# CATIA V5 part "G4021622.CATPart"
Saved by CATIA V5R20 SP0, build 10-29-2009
Part number: G4021622
Revision: 12
Definition: design
Nomenclature: G4021622
Source: made
Description: NOT SPECIFIED
Bounding box of the stored display mesh (mm): x -12 to 22, y -12.803 to 12.803, z -13 to 13
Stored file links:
  C:\Users\Raffaele\Desktop\3D X SITO CF\BOLEX\26-BUSH REF 402\G4021622.CATPart
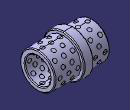
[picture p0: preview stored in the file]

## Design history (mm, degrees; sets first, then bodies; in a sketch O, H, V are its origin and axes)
Body1 "MANIFOLD_SOLID_BREP #9131" (main body)
  Solid1: solid without history
Body2 "MANIFOLD_SOLID_BREP #9274"
  Solid2: solid without history
Body3 "MANIFOLD_SOLID_BREP #9417"
  Solid3: solid without history
Body4 "MANIFOLD_SOLID_BREP #9560"
  Solid4: solid without history
Body5 "MANIFOLD_SOLID_BREP #9703"
  Solid5: solid without history
Body6 "MANIFOLD_SOLID_BREP #9848"
  Solid6: solid without history
Body7 "MANIFOLD_SOLID_BREP #9993"
  Solid7: solid without history
Body8 "MANIFOLD_SOLID_BREP #10138"
  Solid8: solid without history
Body9 "MANIFOLD_SOLID_BREP #10283"
  Solid9: solid without history
Body10 "MANIFOLD_SOLID_BREP #10428"
  Solid10: solid without history
Body11 "MANIFOLD_SOLID_BREP #10573"
  Solid11: solid without history
Body12 "MANIFOLD_SOLID_BREP #10718"
  Solid12: solid without history
Body13 "MANIFOLD_SOLID_BREP #10863"
  Solid13: solid without history
Body14 "MANIFOLD_SOLID_BREP #11008"
  Solid14: solid without history
Body15 "MANIFOLD_SOLID_BREP #11153"
  Solid15: solid without history
Body16 "MANIFOLD_SOLID_BREP #11298"
  Solid16: solid without history
Body17 "MANIFOLD_SOLID_BREP #11443"
  Solid17: solid without history
Body18 "MANIFOLD_SOLID_BREP #11586"
  Solid18: solid without history
Body19 "MANIFOLD_SOLID_BREP #11729"
  Solid19: solid without history
Body20 "MANIFOLD_SOLID_BREP #11872"
  Solid20: solid without history
Body21 "MANIFOLD_SOLID_BREP #12016"
  Solid21: solid without history
Body22 "MANIFOLD_SOLID_BREP #12161"
  Solid22: solid without history
Body23 "MANIFOLD_SOLID_BREP #12304"
  Solid23: solid without history
Body24 "MANIFOLD_SOLID_BREP #12448"
  Solid24: solid without history
Body25 "MANIFOLD_SOLID_BREP #12593"
  Solid25: solid without history
Body26 "MANIFOLD_SOLID_BREP #12738"
  Solid26: solid without history
Body27 "MANIFOLD_SOLID_BREP #12883"
  Solid27: solid without history
Body28 "MANIFOLD_SOLID_BREP #13028"
  Solid28: solid without history
Body29 "MANIFOLD_SOLID_BREP #13173"
  Solid29: solid without history
Body30 "MANIFOLD_SOLID_BREP #13318"
  Solid30: solid without history
Body31 "MANIFOLD_SOLID_BREP #13463"
  Solid31: solid without history
Body32 "MANIFOLD_SOLID_BREP #13606"
  Solid32: solid without history
Body33 "MANIFOLD_SOLID_BREP #13749"
  Solid33: solid without history
Body34 "MANIFOLD_SOLID_BREP #13892"
  Solid34: solid without history
Body35 "MANIFOLD_SOLID_BREP #14035"
  Solid35: solid without history
Body36 "MANIFOLD_SOLID_BREP #14178"
  Solid36: solid without history
Body37 "MANIFOLD_SOLID_BREP #14322"
  Solid37: solid without history
Body38 "MANIFOLD_SOLID_BREP #14467"
  Solid38: solid without history
Body39 "MANIFOLD_SOLID_BREP #14610"
  Solid39: solid without history
Body40 "MANIFOLD_SOLID_BREP #14754"
  Solid40: solid without history
Body41 "MANIFOLD_SOLID_BREP #14899"
  Solid41: solid without history
Body42 "MANIFOLD_SOLID_BREP #15044"
  Solid42: solid without history
Body43 "MANIFOLD_SOLID_BREP #15189"
  Solid43: solid without history
Body44 "MANIFOLD_SOLID_BREP #15334"
  Solid44: solid without history
Body45 "MANIFOLD_SOLID_BREP #15479"
  Solid45: solid without history
Body46 "MANIFOLD_SOLID_BREP #15624"
  Solid46: solid without history
Body47 "MANIFOLD_SOLID_BREP #15769"
  Solid47: solid without history
Body48 "MANIFOLD_SOLID_BREP #15914"
  Solid48: solid without history
Body49 "MANIFOLD_SOLID_BREP #16059"
  Solid49: solid without history
Body50 "MANIFOLD_SOLID_BREP #16204"
  Solid50: solid without history
Body51 "MANIFOLD_SOLID_BREP #16349"
  Solid51: solid without history
Body52 "MANIFOLD_SOLID_BREP #16494"
  Solid52: solid without history
Body53 "MANIFOLD_SOLID_BREP #16639"
  Solid53: solid without history
Body54 "MANIFOLD_SOLID_BREP #16782"
  Solid54: solid without history
Body55 "MANIFOLD_SOLID_BREP #16925"
  Solid55: solid without history
Body56 "MANIFOLD_SOLID_BREP #17068"
  Solid56: solid without history
Body57 "MANIFOLD_SOLID_BREP #17211"
  Solid57: solid without history
Body58 "MANIFOLD_SOLID_BREP #17354"
  Solid58: solid without history
Body59 "MANIFOLD_SOLID_BREP #17497"
  Solid59: solid without history
Body60 "MANIFOLD_SOLID_BREP #17640"
  Solid60: solid without history
Body61 "MANIFOLD_SOLID_BREP #17784"
  Solid61: solid without history
Body62 "MANIFOLD_SOLID_BREP #17929"
  Solid62: solid without history
Body63 "MANIFOLD_SOLID_BREP #18072"
  Solid63: solid without history
Body64 "MANIFOLD_SOLID_BREP #18216"
  Solid64: solid without history
Body65 "MANIFOLD_SOLID_BREP #18361"
  Solid65: solid without history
